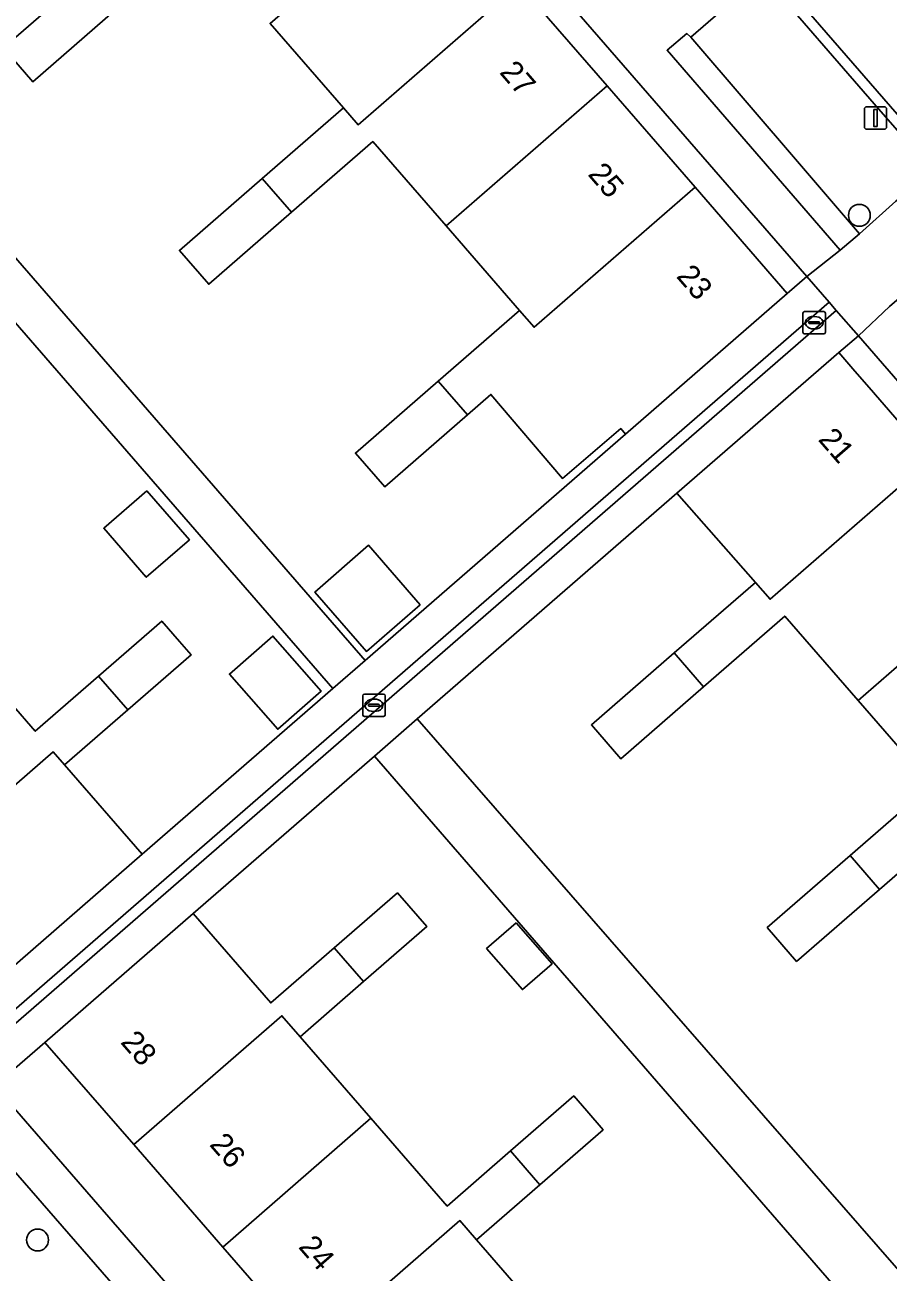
# Model space of a CAD drawing. Extents: x 155887 to 156869, y 383880 to 384678.
# Drawn here: x 156629.4 to 156668, y 384052 to 384107.7 of the extents above; entities that cross this region are included whole.
import ezdxf

# ---------------------------------------------------------------- set-up
doc = ezdxf.new("R2010")
doc.units = 0
for name, color, linetype in [('IMGEO_Boom', 7, 'Continuous'), ('IMGEO_Erf', 7, 'Continuous'), ('IMGEO_Groenvoorziening', 7, 'Continuous'), ('IMGEO_Haag', 7, 'Continuous'), ('IMGEO_Kolk', 7, 'Continuous'), ('IMGEO_Lichtmast', 7, 'Continuous'), ('IMGEO_Pand', 7, 'Continuous'), ('IMGEO_Pand_nummerreeks', 7, 'Continuous'), ('IMGEO_Parkeervlak_open', 7, 'Continuous'), ('IMGEO_Rijbaan_lokaal_gesloten', 7, 'Continuous'), ('IMGEO_Voetpad_open', 7, 'Continuous')]:
    doc.layers.add(name, color=color, linetype=linetype)

msp = doc.modelspace()

# ---------------------------------------------------------------- linework, layer by layer
at = {"layer": 'IMGEO_Boom'}
for centre in [(156666.716, 384099.198), (156629.964, 384053.401)]:
    msp.add_circle(centre, 0.489, dxfattribs=at)
at = {"layer": 'IMGEO_Erf'}
for points in [[(156599.132, 384113.164), (156608.489, 384121.292), (156617.846, 384129.421), (156627.191, 384137.539), (156631.854, 384132.164), (156635.784, 384127.635), (156639.715, 384123.104), (156643.645, 384118.575), (156647.577, 384114.044), (156651.506, 384109.515), (156655.438, 384104.984), (156659.368, 384100.453), (156663.489, 384095.704), (156664.364, 384096.46), (156626.242, 384140.297), (156587.667, 384106.816), (156589.344, 384104.881), (156593.045, 384100.611), (156593.133, 384100.673), (156589.53, 384104.822)], [(156634.849, 384086.883), (156636.75, 384084.695), (156634.824, 384083.023), (156632.924, 384085.211)], [(156647.076, 384081.792), (156644.673, 384079.704), (156642.363, 384082.363), (156644.766, 384084.451)], [(156640.485, 384080.393), (156642.644, 384077.929), (156640.702, 384076.228), (156638.543, 384078.691)], [(156651.372, 384067.58), (156652.969, 384065.75), (156651.643, 384064.594), (156650.046, 384066.424)], [(156646.204, 384043.928), (156642.223, 384048.506), (156638.243, 384053.084), (156634.262, 384057.662), (156630.286, 384062.235), (156628.032, 384060.288), (156663.829, 384019.095), (156666.095, 384021.051), (156662.126, 384025.616), (156658.145, 384030.194), (156654.165, 384034.772), (156650.184, 384039.35)]]:
    msp.add_lwpolyline(points, close=True, dxfattribs=at)
for points in [[(156612.746, 384115.979), (156644.608, 384079.3), (156656.256, 384089.418), (156656.046, 384089.664), (156653.438, 384087.438), (156650.234, 384091.191), (156649.192, 384090.285), (156645.488, 384087.066), (156644.177, 384088.575), (156647.879, 384091.793), (156651.51, 384094.948), (156648.23, 384098.722), (156644.953, 384102.493), (156641.323, 384099.338), (156637.619, 384096.119), (156636.308, 384097.628), (156640.011, 384100.846), (156643.641, 384104.002), (156640.361, 384107.775)], [(156626.671, 384079.81), (156629.857, 384076.142), (156632.688, 384078.602), (156635.519, 384081.061), (156636.311, 384080.149), (156636.831, 384079.551), (156634, 384077.092), (156631.169, 384074.633), (156634.638, 384070.639), (156643.166, 384078.047), (156611.304, 384114.726)], [(156633.453, 384108.39), (156629.75, 384105.172), (156628.439, 384106.681), (156632.142, 384109.899)], [(156702.45, 384052.606), (156666.669, 384093.809), (156665.791, 384093.061), (156666.511, 384092.232), (156667.149, 384091.498), (156669.93, 384088.298)], [(156671.246, 384072.227), (156667.615, 384069.072), (156663.909, 384065.853), (156662.598, 384067.363), (156666.303, 384070.582), (156669.934, 384073.737), (156666.655, 384077.511), (156663.377, 384081.285), (156659.746, 384078.13), (156656.04, 384074.91), (156654.729, 384076.42), (156658.434, 384079.639), (156662.065, 384082.794), (156658.559, 384086.776), (156646.945, 384076.691), (156671.041, 384049.103)], [(156674.565, 384041.006), (156645.025, 384075.023), (156636.922, 384067.987), (156640.393, 384063.995), (156643.223, 384066.456), (156646.053, 384068.916), (156646.559, 384068.334), (156647.365, 384067.407), (156644.535, 384064.947), (156641.705, 384062.486), (156644.872, 384058.843), (156648.285, 384054.918), (156651.115, 384057.379), (156653.945, 384059.839), (156654.52, 384059.178), (156655.257, 384058.33), (156652.428, 384055.87), (156649.598, 384053.409), (156652.834, 384049.687)]]:
    msp.add_lwpolyline(points, dxfattribs=at)
at = {"layer": 'IMGEO_Groenvoorziening'}
msp.add_lwpolyline([(156659.171, 384107.166), (156658.994, 384107.319), (156658.119, 384106.58), (156665.856, 384097.643), (156666.72, 384098.374), (156664.131, 384101.394)], close=True, dxfattribs=at)
at = {"layer": 'IMGEO_Haag'}
msp.add_lwpolyline([(156664.131, 384101.394), (156659.171, 384107.166), (156658.994, 384107.319), (156658.119, 384106.58), (156665.856, 384097.643), (156666.72, 384098.374)], close=True, dxfattribs=at)
at = {"layer": 'IMGEO_Kolk'}
for p, q in [((156664.193, 384093.974), (156664.193, 384094.826)), ((156664.268, 384094.9), (156665.12, 384094.9)), ((156665.194, 384094.826), (156665.194, 384093.974)), ((156664.452, 384094.394), (156664.452, 384094.406)), ((156664.89, 384094.357), (156664.492, 384094.357)), ((156664.495, 384094.443), (156664.893, 384094.443)), ((156664.681, 384094.68), (156664.706, 384094.68)), ((156664.936, 384094.406), (156664.936, 384094.394)), ((156665.12, 384093.9), (156664.268, 384093.9)), ((156664.704, 384094.12), (156664.679, 384094.12)), ((156644.507, 384076.874), (156644.507, 384077.726)), ((156644.582, 384077.8), (156645.434, 384077.8)), ((156644.995, 384077.58), (156645.02, 384077.58)), ((156645.508, 384077.726), (156645.508, 384076.874)), ((156644.766, 384077.294), (156644.766, 384077.306)), ((156645.204, 384077.257), (156644.806, 384077.257)), ((156644.809, 384077.343), (156645.207, 384077.343)), ((156645.018, 384077.02), (156644.993, 384077.02)), ((156645.25, 384077.306), (156645.25, 384077.294)), ((156645.434, 384076.8), (156644.582, 384076.8))]:
    msp.add_line(p, q, dxfattribs=at)
for points in [[(156664.193, 384093.974), (156664.193, 384094.826)], [(156664.268, 384094.9), (156665.12, 384094.9)], [(156665.194, 384094.826), (156665.194, 384093.974)], [(156665.12, 384093.9), (156664.268, 384093.9)], [(156644.507, 384076.874), (156644.507, 384077.726)], [(156644.582, 384077.8), (156645.434, 384077.8)], [(156645.508, 384077.726), (156645.508, 384076.874)], [(156645.434, 384076.8), (156644.582, 384076.8)]]:
    msp.add_lwpolyline(points, dxfattribs=at)
for centre, radius, start, end in [((156664.27, 384094.824), 0.0765, 91.552, 178.448), ((156664.27, 384094.824), 0.0765, 91.552, 178.448), ((156665.118, 384094.824), 0.0765, 1.552, 88.448), ((156665.118, 384094.824), 0.0765, 1.552, 88.448), ((156664.492, 384094.403), 0.0403, 85.8775, 175.7526), ((156664.489, 384094.393), 0.0366, 178.938, 274.7102), ((156664.893, 384094.4), 0.043, 264.8664, 352.4533), ((156664.897, 384094.405), 0.0386, 1.7309, 96.639), ((156664.27, 384093.976), 0.0765, 181.552, 268.448), ((156664.27, 384093.976), 0.0765, 181.552, 268.448), ((156665.118, 384093.976), 0.0765, 271.552, 358.448), ((156665.118, 384093.976), 0.0765, 271.552, 358.448), ((156644.584, 384077.724), 0.0765, 91.552, 178.448), ((156644.584, 384077.724), 0.0765, 91.552, 178.448), ((156645.432, 384077.724), 0.0765, 1.552, 88.448), ((156645.432, 384077.724), 0.0765, 1.552, 88.448), ((156644.584, 384076.876), 0.0765, 181.552, 268.448), ((156644.584, 384076.876), 0.0765, 181.552, 268.448), ((156644.806, 384077.303), 0.0403, 85.8775, 175.7526), ((156644.803, 384077.293), 0.0366, 178.938, 274.7102), ((156645.207, 384077.3), 0.043, 264.8664, 352.4533), ((156645.211, 384077.305), 0.0386, 1.7309, 96.639), ((156645.432, 384076.876), 0.0765, 271.552, 358.448), ((156645.432, 384076.876), 0.0765, 271.552, 358.448)]:
    msp.add_arc(centre, radius, start, end, dxfattribs=at)
for centre, major_axis, ratio, start_param, end_param in [((156664.68, 384094.4), (-0.387, 0.002), 0.722429, 4.712389, 7.853982), ((156664.705, 384094.4), (-0.39, 0.002), 0.717154, 1.570796, 4.712389), ((156644.994, 384077.3), (-0.387, 0.002), 0.722429, 4.712389, 7.853982), ((156645.019, 384077.3), (-0.39, 0.002), 0.717154, 1.570796, 4.712389)]:
    msp.add_ellipse(centre, major_axis=major_axis, ratio=ratio, start_param=start_param, end_param=end_param, dxfattribs=at)
at = {"layer": 'IMGEO_Lichtmast'}
for p, q in [((156666.94, 384103.149), (156666.94, 384103.949)), ((156666.94, 384103.949), (156666.94, 384103.149)), ((156667.04, 384104.049), (156667.83, 384104.049)), ((156667.83, 384104.049), (156667.04, 384104.049)), ((156667.93, 384103.949), (156667.93, 384103.149)), ((156667.93, 384103.149), (156667.93, 384103.949)), ((156667.83, 384103.049), (156667.04, 384103.049)), ((156667.04, 384103.049), (156667.83, 384103.049))]:
    msp.add_line(p, q, dxfattribs=at)
msp.add_lwpolyline([(156667.36, 384103.924), (156667.51, 384103.924), (156667.51, 384103.174), (156667.36, 384103.174), (156667.36, 384103.924)], dxfattribs=at)
for centre, start, end in [((156667.04, 384103.949), 90, 180), ((156667.04, 384103.949), 90, 180), ((156667.83, 384103.949), 0, 90), ((156667.83, 384103.949), 360, 90), ((156667.04, 384103.149), 180, 270), ((156667.04, 384103.149), 180, 270), ((156667.83, 384103.149), 270, 0), ((156667.83, 384103.149), 270, 0)]:
    msp.add_arc(centre, 0.1, start, end, dxfattribs=at)
at = {"layer": 'IMGEO_Pand'}
for points in [[(156651.506, 384109.515), (156647.577, 384114.044), (156640.361, 384107.775), (156643.641, 384104.002), (156644.297, 384103.247)], [(156632.142, 384109.899), (156628.439, 384106.681), (156629.75, 384105.172), (156633.453, 384108.39)], [(156648.23, 384098.722), (156655.438, 384104.984), (156651.506, 384109.515), (156644.297, 384103.247), (156643.641, 384104.002), (156640.011, 384100.846), (156641.323, 384099.338), (156644.953, 384102.493)], [(156648.23, 384098.722), (156651.51, 384094.948), (156652.166, 384094.194), (156659.368, 384100.453), (156655.438, 384104.984)], [(156641.323, 384099.338), (156640.011, 384100.846), (156636.308, 384097.628), (156637.619, 384096.119)], [(156663.489, 384095.704), (156659.368, 384100.453), (156652.166, 384094.194), (156651.51, 384094.948), (156647.879, 384091.793), (156649.192, 384090.285), (156650.234, 384091.191), (156653.438, 384087.438), (156656.046, 384089.664), (156656.256, 384089.418)], [(156662.065, 384082.794), (156662.721, 384082.039), (156669.93, 384088.298), (156667.149, 384091.498), (156666.511, 384092.232), (156665.791, 384093.061), (156658.559, 384086.776)], [(156647.879, 384091.793), (156644.177, 384088.575), (156645.488, 384087.066), (156649.192, 384090.285)], [(156666.655, 384077.511), (156673.865, 384083.769), (156671.349, 384086.665), (156670.571, 384087.56), (156669.93, 384088.298), (156662.721, 384082.039), (156662.065, 384082.794), (156658.434, 384079.639), (156659.746, 384078.13), (156663.377, 384081.285)], [(156634.849, 384086.883), (156632.924, 384085.211), (156634.824, 384083.023), (156636.75, 384084.695)], [(156647.076, 384081.792), (156644.766, 384084.451), (156642.363, 384082.363), (156644.673, 384079.704)], [(156666.655, 384077.511), (156669.934, 384073.737), (156670.59, 384072.982), (156677.799, 384079.24), (156675.423, 384081.975), (156674.515, 384083.021), (156673.865, 384083.769)], [(156636.831, 384079.551), (156636.311, 384080.149), (156635.519, 384081.061), (156632.688, 384078.602), (156634, 384077.092)], [(156642.644, 384077.929), (156640.485, 384080.393), (156638.543, 384078.691), (156640.702, 384076.228)], [(156626.671, 384079.81), (156620.042, 384074.04), (156624.025, 384069.455), (156630.654, 384075.225), (156631.169, 384074.633), (156634, 384077.092), (156632.688, 384078.602), (156629.857, 384076.142)], [(156658.434, 384079.639), (156654.729, 384076.42), (156656.04, 384074.91), (156659.746, 384078.13)], [(156667.615, 384069.072), (156671.246, 384072.227), (156674.525, 384068.453), (156681.735, 384074.71), (156679.36, 384077.444), (156678.447, 384078.495), (156677.799, 384079.24), (156670.59, 384072.982), (156669.934, 384073.737), (156666.303, 384070.582)], [(156631.169, 384074.633), (156630.654, 384075.225), (156624.025, 384069.455), (156628.001, 384064.879), (156634.638, 384070.639)], [(156667.615, 384069.072), (156666.303, 384070.582), (156662.598, 384067.363), (156663.909, 384065.853)], [(156647.365, 384067.407), (156646.559, 384068.334), (156646.053, 384068.916), (156643.223, 384066.456), (156644.535, 384064.947)], [(156636.922, 384067.987), (156630.286, 384062.235), (156634.262, 384057.662), (156640.892, 384063.421), (156641.705, 384062.486), (156644.535, 384064.947), (156643.223, 384066.456), (156640.393, 384063.995)], [(156651.372, 384067.58), (156650.046, 384066.424), (156651.643, 384064.594), (156652.969, 384065.75)], [(156641.705, 384062.486), (156640.892, 384063.421), (156634.262, 384057.662), (156638.243, 384053.084), (156644.872, 384058.843)], [(156655.257, 384058.33), (156654.52, 384059.178), (156653.945, 384059.839), (156651.115, 384057.379), (156652.428, 384055.87)], [(156644.872, 384058.843), (156638.243, 384053.084), (156642.223, 384048.506), (156648.853, 384054.266), (156649.598, 384053.409), (156652.428, 384055.87), (156651.115, 384057.379), (156648.285, 384054.918)], [(156649.598, 384053.409), (156648.853, 384054.266), (156642.223, 384048.506), (156646.204, 384043.928), (156652.834, 384049.687)]]:
    msp.add_lwpolyline(points, close=True, dxfattribs=at)
at = {"layer": 'IMGEO_Parkeervlak_open'}
for points in [[(156659.171, 384107.166), (156664.131, 384101.394), (156666.72, 384098.374), (156668.347, 384099.827), (156669.957, 384101.21), (156668.515, 384102.891), (156667.373, 384104.188), (156662.385, 384109.95)], [(156628.486, 384056.983), (156626.59, 384059.141), (156624.722, 384057.535), (156623.112, 384056.157), (156624.566, 384054.471), (156625.01, 384053.951), (156634.535, 384043.005), (156638.005, 384046.033)]]:
    msp.add_lwpolyline(points, close=True, dxfattribs=at)
at = {"layer": 'IMGEO_Rijbaan_lokaal_gesloten'}
for points in [[(156634.265, 384142.334), (156635.094, 384141.353), (156645.276, 384129.637), (156646.591, 384128.125), (156648.334, 384126.107), (156653.088, 384120.655), (156654.396, 384119.142), (156661.071, 384111.467), (156662.385, 384109.95), (156667.373, 384104.188), (156668.515, 384102.891), (156669.957, 384101.21), (156672.182, 384098.688), (156673.627, 384097.017), (156674.784, 384095.678), (156679.734, 384089.985), (156681.066, 384088.468), (156686.032, 384082.758), (156687.753, 384080.745), (156689.082, 384079.232), (156695.457, 384071.872), (156696.778, 384070.365), (156704.9, 384061.019)], [(156707.089, 384059.25), (156688.102, 384081.041), (156680.796, 384089.479), (156662.154, 384110.91), (156634.612, 384142.629)]]:
    msp.add_lwpolyline(points, dxfattribs=at)
at = {"layer": 'IMGEO_Voetpad_open'}
for points in [[(156634.612, 384142.629), (156662.154, 384110.91), (156680.796, 384089.479), (156688.102, 384081.041), (156707.089, 384059.25), (156708.358, 384057.797), (156710.535, 384055.305), (156710.605, 384055.225)], [(156626.242, 384140.297), (156664.364, 384096.46), (156665.856, 384097.643), (156658.119, 384106.58), (156658.994, 384107.319), (156659.171, 384107.166), (156662.385, 384109.95)], [(156668.067, 384095.129), (156666.669, 384093.809), (156702.45, 384052.606)], [(156628.486, 384056.983), (156638.005, 384046.033), (156634.535, 384043.005), (156635.452, 384041.937), (156638.929, 384044.96), (156649.798, 384032.429), (156646.311, 384029.397), (156647.553, 384027.982), (156651.076, 384031.003), (156662.415, 384017.868), (156663.829, 384019.095), (156628.032, 384060.288)]]:
    msp.add_lwpolyline(points, dxfattribs=at)
for points in [[(156612.746, 384115.979), (156624.624, 384125.881), (156623.575, 384127.088), (156621.464, 384125.256), (156612.102, 384117.132), (156602.741, 384109.01), (156593.133, 384100.673), (156593.045, 384100.611), (156593.911, 384099.613), (156596.143, 384101.55), (156602.78, 384107.311), (156611.304, 384114.726), (156643.166, 384078.047), (156644.608, 384079.3)], [(156672.182, 384098.688), (156669.957, 384101.21), (156668.347, 384099.827), (156666.72, 384098.374), (156665.856, 384097.643), (156664.364, 384096.46), (156665.358, 384095.323), (156665.67, 384094.951), (156666.669, 384093.809), (156668.067, 384095.129), (156668.925, 384095.867), (156670.596, 384097.314)], [(156665.358, 384095.323), (156664.364, 384096.46), (156663.489, 384095.704), (156656.256, 384089.418), (156644.608, 384079.3), (156643.166, 384078.047), (156634.638, 384070.639), (156628.001, 384064.879), (156625.75, 384062.919), (156626.735, 384061.795)], [(156665.67, 384094.951), (156665.358, 384095.323), (156626.735, 384061.795), (156627.051, 384061.422)], [(156636.922, 384067.987), (156645.025, 384075.023), (156646.945, 384076.691), (156658.559, 384086.776), (156665.791, 384093.061), (156666.669, 384093.809), (156665.67, 384094.951), (156627.051, 384061.422), (156628.032, 384060.288), (156630.286, 384062.235)], [(156646.945, 384076.691), (156645.025, 384075.023), (156674.565, 384041.006), (156674.785, 384041.198), (156676.887, 384038.78), (156676.665, 384038.587), (156677.751, 384037.337), (156680.639, 384034.016), (156680.803, 384033.827), (156682.932, 384035.678), (156682.767, 384035.867), (156679.879, 384039.187), (156674.64, 384044.933), (156671.041, 384049.103)]]:
    msp.add_lwpolyline(points, close=True, dxfattribs=at)

# ---------------------------------------------------------------- texts
at = {"layer": 'IMGEO_Pand_nummerreeks'}
for s, rotation, p in [('27', 310.9464, (156650.585, 384105.572)), ('25', 310.9464, (156654.539, 384101.015)), ('23', 310.9491, (156658.493, 384096.457)), ('21', 310.9865, (156664.837, 384089.16)), ('28', 311.0064, (156633.638, 384062.222)), ('26', 311.0064, (156637.615, 384057.649)), ('24', 311.0064, (156641.593, 384053.073))]:
    msp.add_text(s, height=1, rotation=rotation, dxfattribs=at).set_placement(p)

doc.saveas('drawing.dxf')
